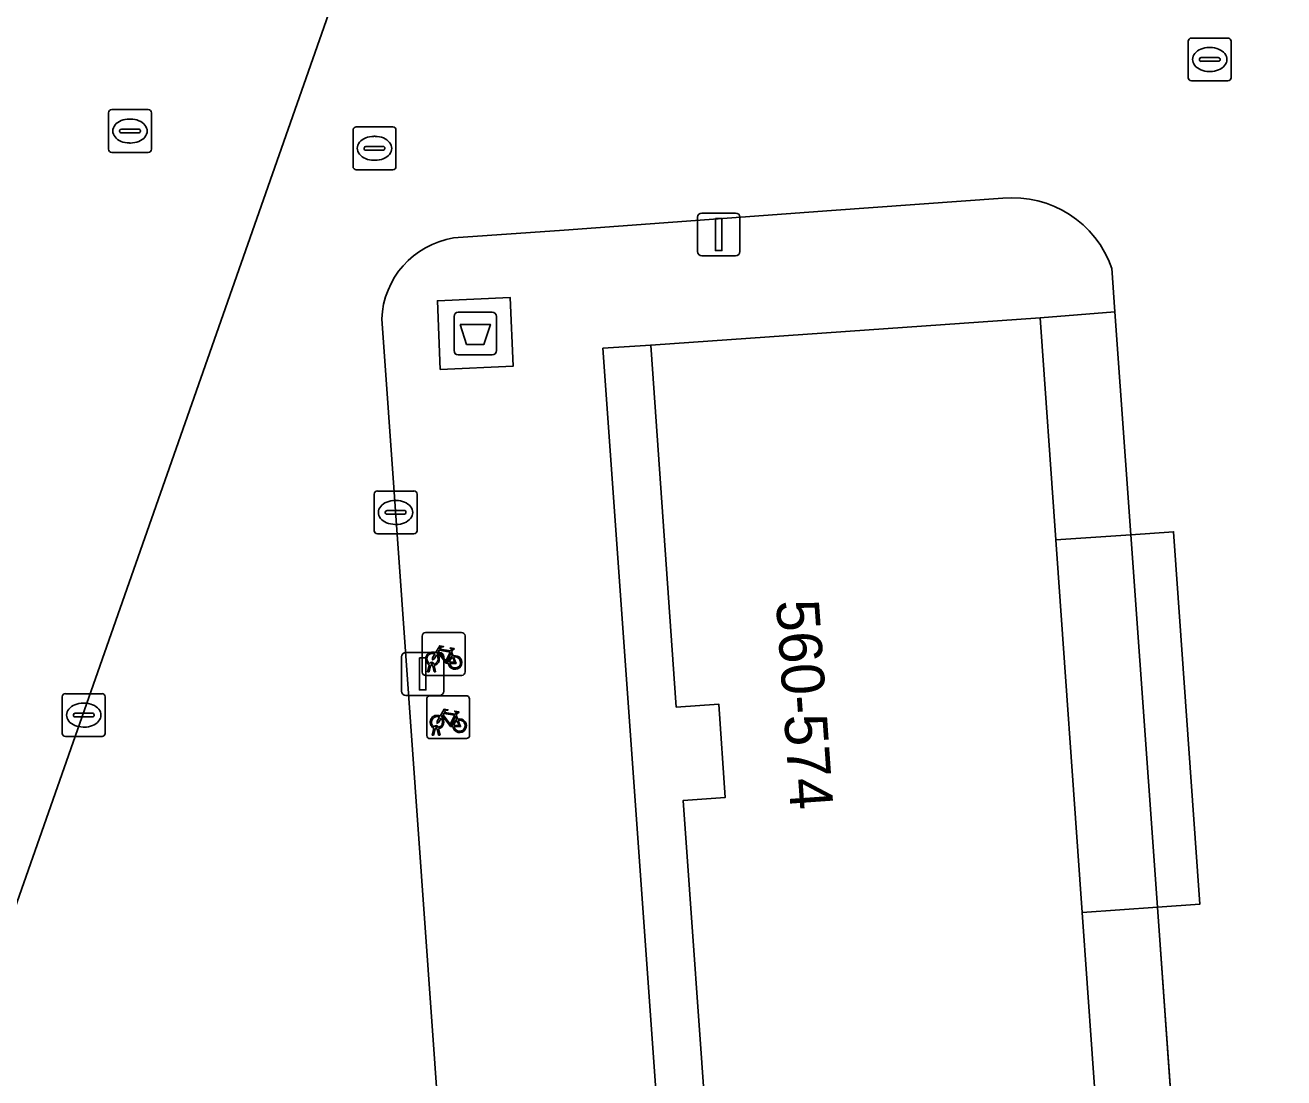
# Model space of a CAD drawing. Extents: x 161248 to 161848, y 384871 to 385383.
# Drawn here: x 161748.82 to 161778.18, y 385173.89 to 385198.45 of the extents above; entities that cross this region are included whole.
import ezdxf

# ---------------------------------------------------------------- set-up
doc = ezdxf.new("R2010")
doc.units = 0
for name, color, linetype in [('IMGEO_Afval_apart_plaats', 7, 'Continuous'), ('IMGEO_Fietsenrek', 7, 'Continuous'), ('IMGEO_Kolk', 7, 'Continuous'), ('IMGEO_Lichtmast', 7, 'Continuous'), ('IMGEO_Pand', 7, 'Continuous'), ('IMGEO_Pand_nummerreeks', 7, 'Continuous'), ('IMGEO_Pand_overbouw', 7, 'Continuous'), ('IMGEO_Rijbaan_lokaal_open', 7, 'Continuous'), ('IMGEO_Rioolput', 7, 'Continuous'), ('IMGEO_Voetpad_gesloten', 7, 'Continuous'), ('IMGEO_Voetpad_open', 7, 'Continuous')]:
    doc.layers.add(name, color=color, linetype=linetype)

msp = doc.modelspace()

# ---------------------------------------------------------------- linework, layer by layer
at = {"layer": 'IMGEO_Afval_apart_plaats'}
for p, q in [((161758.924, 385191.757), (161759.714, 385191.757)), ((161759.714, 385191.757), (161758.924, 385191.757)), ((161758.824, 385190.857), (161758.824, 385191.657)), ((161758.824, 385191.657), (161758.824, 385190.857)), ((161759.814, 385191.657), (161759.814, 385190.857)), ((161759.814, 385190.857), (161759.814, 385191.657)), ((161759.714, 385190.757), (161758.924, 385190.757)), ((161758.924, 385190.757), (161759.714, 385190.757))]:
    msp.add_line(p, q, dxfattribs=at)
msp.add_lwpolyline([(161758.967, 385191.471), (161759.671, 385191.471), (161759.522, 385191.001), (161759.116, 385191.001), (161758.967, 385191.471)], dxfattribs=at)
for centre, start, end in [((161758.924, 385191.657), 90, 180), ((161758.924, 385191.657), 90, 180), ((161759.714, 385191.657), 0, 90), ((161759.714, 385191.657), 360, 90), ((161758.924, 385190.857), 180, 270), ((161758.924, 385190.857), 180, 270), ((161759.714, 385190.857), 270, 0), ((161759.714, 385190.857), 270, 0)]:
    msp.add_arc(centre, 0.1, start, end, dxfattribs=at)
at = {"layer": 'IMGEO_Fietsenrek'}
for p, q in [((161758.081, 385183.355), (161758.081, 385184.196)), ((161758.081, 385184.196), (161758.081, 385183.355)), ((161758.156, 385184.28), (161758.997, 385184.28)), ((161758.997, 385184.28), (161758.156, 385184.28)), ((161759.081, 385184.205), (161759.081, 385183.364)), ((161759.081, 385183.364), (161759.081, 385184.205)), ((161758.768, 385183.829), (161758.804, 385183.734)), ((161758.208, 385183.364), (161758.247, 385183.524)), ((161758.277, 385183.512), (161758.242, 385183.364)), ((161758.319, 385183.536), (161758.318, 385183.54)), ((161758.36, 385183.364), (161758.326, 385183.506)), ((161758.35, 385183.547), (161758.351, 385183.54)), ((161758.358, 385183.51), (161758.393, 385183.364)), ((161759.006, 385183.28), (161758.165, 385183.28)), ((161758.165, 385183.28), (161759.006, 385183.28)), ((161758.242, 385183.364), (161758.208, 385183.364)), ((161758.393, 385183.364), (161758.36, 385183.364)), ((161758.186, 385181.879), (161758.186, 385182.72)), ((161758.186, 385182.72), (161758.186, 385181.879)), ((161758.261, 385182.804), (161759.102, 385182.804)), ((161759.102, 385182.804), (161758.261, 385182.804)), ((161759.186, 385182.729), (161759.186, 385181.888)), ((161759.186, 385181.888), (161759.186, 385182.729)), ((161758.873, 385182.353), (161758.909, 385182.258)), ((161758.313, 385181.888), (161758.352, 385182.048)), ((161758.382, 385182.036), (161758.347, 385181.888)), ((161758.424, 385182.06), (161758.423, 385182.064)), ((161758.465, 385181.888), (161758.431, 385182.03)), ((161758.455, 385182.071), (161758.456, 385182.064)), ((161758.463, 385182.034), (161758.498, 385181.888)), ((161759.111, 385181.804), (161758.27, 385181.804)), ((161758.27, 385181.804), (161759.111, 385181.804)), ((161758.347, 385181.888), (161758.313, 385181.888)), ((161758.498, 385181.888), (161758.465, 385181.888))]:
    msp.add_line(p, q, dxfattribs=at)
for points in [[(161758.415, 385183.754), (161758.363, 385183.664), (161758.323, 385183.639), (161758.324, 385183.686), (161758.379, 385183.78)], [(161758.394, 385183.806), (161758.489, 385183.97), (161758.575, 385183.956), (161758.577, 385183.947), (161758.521, 385183.936), (161758.494, 385183.891), (161758.75, 385183.85)], [(161758.69, 385183.562), (161758.64, 385183.562), (161758.449, 385183.813), (161758.43, 385183.781)], [(161758.737, 385183.825), (161758.48, 385183.866), (161758.463, 385183.837), (161758.63, 385183.617), (161758.737, 385183.825)], [(161758.785, 385183.727), (161758.755, 385183.804), (161758.646, 385183.586), (161758.689, 385183.586)], [(161758.75, 385183.85), (161758.775, 385183.899), (161758.769, 385183.903), (161758.746, 385183.907), (161758.734, 385183.914), (161758.733, 385183.917), (161758.735, 385183.922), (161758.83, 385183.907), (161758.832, 385183.897), (161758.822, 385183.884), (161758.81, 385183.878), (161758.796, 385183.884), (161758.768, 385183.829)], [(161758.719, 385183.586), (161758.839, 385183.585), (161758.795, 385183.699)], [(161758.815, 385183.706), (161758.87, 385183.561), (161758.72, 385183.561)], [(161758.52, 385182.278), (161758.468, 385182.188), (161758.428, 385182.163), (161758.429, 385182.21), (161758.484, 385182.304)], [(161758.499, 385182.33), (161758.594, 385182.494), (161758.68, 385182.48), (161758.682, 385182.471), (161758.626, 385182.46), (161758.599, 385182.415), (161758.855, 385182.374)], [(161758.795, 385182.086), (161758.745, 385182.086), (161758.554, 385182.337), (161758.535, 385182.305)], [(161758.842, 385182.349), (161758.585, 385182.39), (161758.568, 385182.361), (161758.735, 385182.141), (161758.842, 385182.349)], [(161758.89, 385182.251), (161758.86, 385182.328), (161758.751, 385182.11), (161758.794, 385182.11)], [(161758.855, 385182.374), (161758.88, 385182.423), (161758.874, 385182.427), (161758.851, 385182.431), (161758.839, 385182.438), (161758.838, 385182.441), (161758.84, 385182.446), (161758.935, 385182.431), (161758.937, 385182.421), (161758.927, 385182.408), (161758.915, 385182.402), (161758.901, 385182.408), (161758.873, 385182.353)], [(161758.824, 385182.11), (161758.944, 385182.109), (161758.9, 385182.223)], [(161758.92, 385182.23), (161758.975, 385182.085), (161758.825, 385182.085)]]:
    msp.add_lwpolyline(points, dxfattribs=at)
for centre, radius, start, end in [((161758.159, 385184.202), 0.0779, 92.4484, 184.2845), ((161758.159, 385184.202), 0.0779, 92.4484, 184.2845), ((161759.003, 385184.202), 0.0779, 2.4484, 94.2845), ((161759.003, 385184.202), 0.0779, 2.4484, 94.2845), ((161758.321, 385183.665), 0.159, 62.6766, 242.1369), ((161758.321, 385183.665), 0.129, 63.3192, 238.903), ((161758.321, 385183.665), 0.129, 283.6043, 43.4302), ((161758.321, 385183.665), 0.159, 283.5766, 46.6042), ((161758.848, 385183.581), 0.159, 187.0065, 105.7708), ((161758.301, 385183.536), 0.0499, 12.8025, 158.6934), ((161758.321, 385183.665), 0.159, 253.9967, 271.7867), ((161758.301, 385183.536), 0.0174, 12.8025, 163.4502), ((161758.321, 385183.665), 0.129, 253.415, 269.0204), ((161758.848, 385183.581), 0.159, 113.3408, 178.3217), ((161758.848, 385183.581), 0.129, 113.923, 177.9556), ((161758.848, 385183.581), 0.129, 188.6715, 104.5883), ((161758.159, 385183.358), 0.0779, 182.4484, 274.2845), ((161758.159, 385183.358), 0.0779, 182.4484, 274.2845), ((161759.003, 385183.358), 0.0779, 272.4484, 4.2845), ((161759.003, 385183.358), 0.0779, 272.4484, 4.2845), ((161758.264, 385182.726), 0.0779, 92.4484, 184.2845), ((161758.264, 385182.726), 0.0779, 92.4484, 184.2845), ((161759.108, 385182.726), 0.0779, 2.4484, 94.2845), ((161759.108, 385182.726), 0.0779, 2.4484, 94.2845), ((161758.426, 385182.189), 0.159, 62.6766, 242.1369), ((161758.426, 385182.189), 0.129, 63.3192, 238.903), ((161758.426, 385182.189), 0.129, 283.6043, 43.4302), ((161758.426, 385182.189), 0.159, 283.5766, 46.6042), ((161758.406, 385182.06), 0.0499, 12.8025, 158.6934), ((161758.426, 385182.189), 0.159, 253.9967, 271.7867), ((161758.406, 385182.06), 0.0174, 12.8025, 163.4502), ((161758.426, 385182.189), 0.129, 253.415, 269.0204), ((161758.953, 385182.105), 0.159, 113.3408, 178.3217), ((161758.953, 385182.105), 0.159, 187.0065, 105.7708), ((161758.953, 385182.105), 0.129, 113.923, 177.9556), ((161758.953, 385182.105), 0.129, 188.6715, 104.5883), ((161758.264, 385181.882), 0.0779, 182.4484, 274.2845), ((161758.264, 385181.882), 0.0779, 182.4484, 274.2845), ((161759.108, 385181.882), 0.0779, 272.4484, 4.2845), ((161759.108, 385181.882), 0.0779, 272.4484, 4.2845)]:
    msp.add_arc(centre, radius, start, end, dxfattribs=at)
at = {"layer": 'IMGEO_Kolk'}
for p, q in [((161757.035, 385187.582), (161757.887, 385187.582)), ((161756.96, 385186.656), (161756.96, 385187.508)), ((161757.448, 385187.362), (161757.473, 385187.362)), ((161757.961, 385187.508), (161757.961, 385186.656)), ((161757.219, 385187.076), (161757.219, 385187.088)), ((161757.657, 385187.039), (161757.259, 385187.039)), ((161757.262, 385187.125), (161757.66, 385187.125)), ((161757.703, 385187.088), (161757.703, 385187.076)), ((161757.471, 385186.802), (161757.446, 385186.802)), ((161757.887, 385186.582), (161757.035, 385186.582)), ((161749.686, 385181.927), (161749.686, 385182.779)), ((161749.761, 385182.853), (161750.613, 385182.853)), ((161750.174, 385182.633), (161750.199, 385182.633)), ((161750.687, 385182.779), (161750.687, 385181.927)), ((161749.945, 385182.347), (161749.945, 385182.359)), ((161750.383, 385182.31), (161749.985, 385182.31)), ((161749.988, 385182.396), (161750.386, 385182.396)), ((161750.429, 385182.359), (161750.429, 385182.347)), ((161750.197, 385182.073), (161750.172, 385182.073)), ((161750.613, 385181.853), (161749.761, 385181.853))]:
    msp.add_line(p, q, dxfattribs=at)
for points in [[(161757.035, 385187.582), (161757.887, 385187.582)], [(161756.96, 385186.656), (161756.96, 385187.508)], [(161757.961, 385187.508), (161757.961, 385186.656)], [(161757.887, 385186.582), (161757.035, 385186.582)], [(161749.686, 385181.927), (161749.686, 385182.779)], [(161749.761, 385182.853), (161750.613, 385182.853)], [(161750.687, 385182.779), (161750.687, 385181.927)], [(161750.613, 385181.853), (161749.761, 385181.853)]]:
    msp.add_lwpolyline(points, dxfattribs=at)
for centre, radius, start, end in [((161757.037, 385187.506), 0.0765, 91.552, 178.448), ((161757.037, 385187.506), 0.0765, 91.552, 178.448), ((161757.885, 385187.506), 0.0765, 1.552, 88.448), ((161757.885, 385187.506), 0.0765, 1.552, 88.448), ((161757.259, 385187.085), 0.0403, 85.8775, 175.7526), ((161757.256, 385187.075), 0.0366, 178.938, 274.7102), ((161757.66, 385187.082), 0.043, 264.8664, 352.4533), ((161757.664, 385187.087), 0.0386, 1.7309, 96.639), ((161757.037, 385186.658), 0.0765, 181.552, 268.448), ((161757.037, 385186.658), 0.0765, 181.552, 268.448), ((161757.885, 385186.658), 0.0765, 271.552, 358.448), ((161757.885, 385186.658), 0.0765, 271.552, 358.448), ((161749.763, 385182.777), 0.0765, 91.552, 178.448), ((161749.763, 385182.777), 0.0765, 91.552, 178.448), ((161750.611, 385182.777), 0.0765, 1.552, 88.448), ((161750.611, 385182.777), 0.0765, 1.552, 88.448), ((161749.985, 385182.356), 0.0403, 85.8775, 175.7526), ((161749.982, 385182.346), 0.0366, 178.938, 274.7102), ((161750.386, 385182.353), 0.043, 264.8664, 352.4533), ((161750.39, 385182.358), 0.0386, 1.7309, 96.639), ((161749.763, 385181.929), 0.0765, 181.552, 268.448), ((161749.763, 385181.929), 0.0765, 181.552, 268.448), ((161750.611, 385181.929), 0.0765, 271.552, 358.448), ((161750.611, 385181.929), 0.0765, 271.552, 358.448)]:
    msp.add_arc(centre, radius, start, end, dxfattribs=at)
for centre, major_axis, ratio, start_param, end_param in [((161757.447, 385187.082), (-0.387, 0.002), 0.722429, 4.712389, 7.853982), ((161757.472, 385187.082), (-0.39, 0.002), 0.717154, 1.570796, 4.712389), ((161750.173, 385182.353), (-0.387, 0.002), 0.722429, 4.712389, 7.853982), ((161750.198, 385182.353), (-0.39, 0.002), 0.717154, 1.570796, 4.712389)]:
    msp.add_ellipse(centre, major_axis=major_axis, ratio=ratio, start_param=start_param, end_param=end_param, dxfattribs=at)
at = {"layer": 'IMGEO_Lichtmast'}
for p, q in [((161764.602, 385194.069), (161765.392, 385194.069)), ((161765.392, 385194.069), (161764.602, 385194.069)), ((161764.502, 385193.169), (161764.502, 385193.969)), ((161764.502, 385193.969), (161764.502, 385193.169)), ((161765.492, 385193.969), (161765.492, 385193.169)), ((161765.492, 385193.169), (161765.492, 385193.969)), ((161765.392, 385193.069), (161764.602, 385193.069)), ((161764.602, 385193.069), (161765.392, 385193.069)), ((161757.697, 385183.814), (161758.487, 385183.814)), ((161758.487, 385183.814), (161757.697, 385183.814)), ((161757.597, 385182.914), (161757.597, 385183.714)), ((161757.597, 385183.714), (161757.597, 385182.914)), ((161758.587, 385183.714), (161758.587, 385182.914)), ((161758.587, 385182.914), (161758.587, 385183.714)), ((161758.487, 385182.814), (161757.697, 385182.814)), ((161757.697, 385182.814), (161758.487, 385182.814))]:
    msp.add_line(p, q, dxfattribs=at)
for points in [[(161764.922, 385193.944), (161765.072, 385193.944), (161765.072, 385193.194), (161764.922, 385193.194), (161764.922, 385193.944)], [(161758.017, 385183.689), (161758.167, 385183.689), (161758.167, 385182.939), (161758.017, 385182.939), (161758.017, 385183.689)]]:
    msp.add_lwpolyline(points, dxfattribs=at)
for centre, start, end in [((161764.602, 385193.969), 90, 180), ((161764.602, 385193.969), 90, 180), ((161765.392, 385193.969), 0, 90), ((161765.392, 385193.969), 360, 90), ((161764.602, 385193.169), 180, 270), ((161764.602, 385193.169), 180, 270), ((161765.392, 385193.169), 270, 0), ((161765.392, 385193.169), 270, 0), ((161757.697, 385183.714), 90, 180), ((161757.697, 385183.714), 90, 180), ((161758.487, 385183.714), 0, 90), ((161758.487, 385183.714), 360, 90), ((161757.697, 385182.914), 180, 270), ((161757.697, 385182.914), 180, 270), ((161758.487, 385182.914), 270, 0), ((161758.487, 385182.914), 270, 0)]:
    msp.add_arc(centre, 0.1, start, end, dxfattribs=at)
at = {"layer": 'IMGEO_Pand'}
msp.add_lwpolyline([(161772.863, 385186.439), (161772.498, 385191.626), (161763.412, 385190.986), (161764.007, 385182.541), (161764.997, 385182.611), (161765.15, 385180.433), (161764.17, 385180.364), (161764.748, 385172.162), (161773.824, 385172.802), (161773.475, 385177.751)], close=True, dxfattribs=at)
at = {"layer": 'IMGEO_Pand_overbouw'}
for points in [[(161774.609, 385186.562), (161774.237, 385191.764), (161772.498, 385191.626), (161772.863, 385186.439), (161773.475, 385177.751), (161773.824, 385172.802), (161775.583, 385172.925), (161775.229, 385177.875)], [(161764.997, 385182.611), (161764.007, 385182.541), (161763.412, 385190.986), (161762.298, 385190.913), (161763.638, 385172.084), (161764.748, 385172.162), (161764.17, 385180.364), (161765.15, 385180.433)]]:
    msp.add_lwpolyline(points, close=True, dxfattribs=at)
at = {"layer": 'IMGEO_Rijbaan_lokaal_open'}
for points in [[(161730.177, 385124.632), (161736.996, 385144.544), (161740.956, 385156.108), (161742.83, 385161.454), (161757.564, 385203.488), (161757.857, 385204.325), (161760.395, 385211.566), (161765.249, 385225.382), (161768.452, 385234.5), (161773.897, 385250), (161777.978, 385261.406), (161780.943, 385269.693), (161785.276, 385281.802), (161785.52, 385282.473), (161785.703, 385283.163), (161785.823, 385283.866), (161785.88, 385284.578), (161785.874, 385285.292), (161785.803, 385286.002), (161785.673, 385286.689), (161785.312, 385289.733), (161785.296, 385289.929), (161784.343, 385297.154)], [(161757.857, 385204.325), (161757.564, 385203.488), (161742.83, 385161.454), (161759.202, 385162.654), (161758.842, 385167.667), (161757.138, 385191.597)], [(161758.811, 385193.486), (161761.389, 385193.667), (161763.401, 385193.815), (161767.63, 385194.127), (161771.625, 385194.413)], [(161774.165, 385192.778), (161774.237, 385191.764), (161774.609, 385186.562), (161775.608, 385186.633), (161776.22, 385177.945), (161775.229, 385177.875), (161775.933, 385168.029), (161776.914, 385168.098), (161777.526, 385159.401), (161776.554, 385159.332), (161777.256, 385149.507), (161778.218, 385149.575), (161778.83, 385140.897), (161777.876, 385140.83), (161778.263, 385135.406), (161778.562, 385131.184), (161779.901, 385131.276)]]:
    msp.add_lwpolyline(points, dxfattribs=at)
msp.add_lwpolyline([(161775.229, 385177.875), (161776.22, 385177.945), (161775.608, 385186.633), (161774.609, 385186.562)], close=True, dxfattribs=at)
for centre, radius, start, end in [((161771.859, 385191.986), 2.438, 18.9534, 95.5078), ((161759.133, 385191.515), 1.997, 99.2802, 177.6601)]:
    msp.add_arc(centre, radius, start, end, dxfattribs=at)
at = {"layer": 'IMGEO_Rioolput'}
for p, q in [((161776.024, 385198.151), (161776.876, 385198.151)), ((161775.949, 385197.225), (161775.949, 385198.077)), ((161776.437, 385197.931), (161776.462, 385197.931)), ((161776.95, 385198.077), (161776.95, 385197.225)), ((161776.208, 385197.645), (161776.208, 385197.657)), ((161776.646, 385197.608), (161776.248, 385197.608)), ((161776.251, 385197.694), (161776.649, 385197.694)), ((161776.692, 385197.657), (161776.692, 385197.645)), ((161776.46, 385197.371), (161776.435, 385197.371)), ((161776.876, 385197.151), (161776.024, 385197.151)), ((161750.765, 385195.556), (161750.765, 385196.408)), ((161750.84, 385196.482), (161751.692, 385196.482)), ((161751.766, 385196.408), (161751.766, 385195.556)), ((161751.253, 385196.262), (161751.278, 385196.262)), ((161756.543, 385196.078), (161757.395, 385196.078)), ((161751.024, 385195.976), (161751.024, 385195.988)), ((161751.462, 385195.939), (161751.064, 385195.939)), ((161751.067, 385196.025), (161751.465, 385196.025)), ((161751.508, 385195.988), (161751.508, 385195.976)), ((161756.468, 385195.152), (161756.468, 385196.004)), ((161756.956, 385195.858), (161756.981, 385195.858)), ((161757.469, 385196.004), (161757.469, 385195.152)), ((161751.276, 385195.702), (161751.251, 385195.702)), ((161756.727, 385195.572), (161756.727, 385195.584)), ((161757.165, 385195.535), (161756.767, 385195.535)), ((161756.77, 385195.621), (161757.168, 385195.621)), ((161757.211, 385195.584), (161757.211, 385195.572)), ((161751.692, 385195.482), (161750.84, 385195.482)), ((161756.979, 385195.298), (161756.954, 385195.298)), ((161757.395, 385195.078), (161756.543, 385195.078))]:
    msp.add_line(p, q, dxfattribs=at)
for points in [[(161776.024, 385198.151), (161776.876, 385198.151)], [(161775.949, 385197.225), (161775.949, 385198.077)], [(161776.95, 385198.077), (161776.95, 385197.225)], [(161776.876, 385197.151), (161776.024, 385197.151)], [(161750.765, 385195.556), (161750.765, 385196.408)], [(161750.84, 385196.482), (161751.692, 385196.482)], [(161751.766, 385196.408), (161751.766, 385195.556)], [(161756.543, 385196.078), (161757.395, 385196.078)], [(161756.468, 385195.152), (161756.468, 385196.004)], [(161757.469, 385196.004), (161757.469, 385195.152)], [(161751.692, 385195.482), (161750.84, 385195.482)], [(161757.395, 385195.078), (161756.543, 385195.078)]]:
    msp.add_lwpolyline(points, dxfattribs=at)
for centre, radius, start, end in [((161776.026, 385198.075), 0.0765, 91.552, 178.448), ((161776.026, 385198.075), 0.0765, 91.552, 178.448), ((161776.874, 385198.075), 0.0765, 1.552, 88.448), ((161776.874, 385198.075), 0.0765, 1.552, 88.448), ((161776.248, 385197.654), 0.0403, 85.8775, 175.7526), ((161776.245, 385197.644), 0.0366, 178.938, 274.7102), ((161776.649, 385197.651), 0.043, 264.8664, 352.4533), ((161776.653, 385197.656), 0.0386, 1.7309, 96.639), ((161776.026, 385197.227), 0.0765, 181.552, 268.448), ((161776.026, 385197.227), 0.0765, 181.552, 268.448), ((161776.874, 385197.227), 0.0765, 271.552, 358.448), ((161776.874, 385197.227), 0.0765, 271.552, 358.448), ((161750.842, 385196.406), 0.0765, 91.552, 178.448), ((161750.842, 385196.406), 0.0765, 91.552, 178.448), ((161751.69, 385196.406), 0.0765, 1.552, 88.448), ((161751.69, 385196.406), 0.0765, 1.552, 88.448), ((161756.545, 385196.002), 0.0765, 91.552, 178.448), ((161756.545, 385196.002), 0.0765, 91.552, 178.448), ((161757.393, 385196.002), 0.0765, 1.552, 88.448), ((161757.393, 385196.002), 0.0765, 1.552, 88.448), ((161751.064, 385195.985), 0.0403, 85.8775, 175.7526), ((161751.061, 385195.975), 0.0366, 178.938, 274.7102), ((161751.465, 385195.982), 0.043, 264.8664, 352.4533), ((161751.469, 385195.987), 0.0386, 1.7309, 96.639), ((161750.842, 385195.558), 0.0765, 181.552, 268.448), ((161750.842, 385195.558), 0.0765, 181.552, 268.448), ((161751.69, 385195.558), 0.0765, 271.552, 358.448), ((161751.69, 385195.558), 0.0765, 271.552, 358.448), ((161756.767, 385195.581), 0.0403, 85.8775, 175.7526), ((161756.764, 385195.571), 0.0366, 178.938, 274.7102), ((161757.168, 385195.578), 0.043, 264.8664, 352.4533), ((161757.172, 385195.583), 0.0386, 1.7309, 96.639), ((161756.545, 385195.154), 0.0765, 181.552, 268.448), ((161756.545, 385195.154), 0.0765, 181.552, 268.448), ((161757.393, 385195.154), 0.0765, 271.552, 358.448), ((161757.393, 385195.154), 0.0765, 271.552, 358.448)]:
    msp.add_arc(centre, radius, start, end, dxfattribs=at)
for centre, major_axis, ratio, start_param, end_param in [((161776.436, 385197.651), (-0.387, 0.002), 0.722429, 4.712389, 7.853982), ((161776.461, 385197.651), (-0.39, 0.002), 0.717154, 1.570796, 4.712389), ((161751.252, 385195.982), (-0.387, 0.002), 0.722429, 4.712389, 7.853982), ((161751.277, 385195.982), (-0.39, 0.002), 0.717154, 1.570796, 4.712389), ((161756.955, 385195.578), (-0.387, 0.002), 0.722429, 4.712389, 7.853982), ((161756.98, 385195.578), (-0.39, 0.002), 0.717154, 1.570796, 4.712389)]:
    msp.add_ellipse(centre, major_axis=major_axis, ratio=ratio, start_param=start_param, end_param=end_param, dxfattribs=at)
at = {"layer": 'IMGEO_Voetpad_gesloten'}
msp.add_lwpolyline([(161760.134, 385192.094), (161758.436, 385192.022), (161758.504, 385190.42), (161760.202, 385190.492)], close=True, dxfattribs=at)
at = {"layer": 'IMGEO_Voetpad_open'}
for points in [[(161771.625, 385194.413), (161767.63, 385194.127), (161763.401, 385193.815), (161761.389, 385193.667), (161758.811, 385193.486)], [(161764.958, 385153.524), (161763.638, 385172.084), (161762.298, 385190.913), (161763.412, 385190.986), (161772.498, 385191.626), (161774.237, 385191.764), (161774.165, 385192.778)], [(161757.138, 385191.597), (161758.842, 385167.667), (161759.202, 385162.654), (161759.984, 385151.748), (161760.378, 385146.252), (161761.09, 385136.334), (161761.126, 385135.828)]]:
    msp.add_lwpolyline(points, dxfattribs=at)
for points in [[(161758.504, 385190.42), (161758.436, 385192.022), (161760.134, 385192.094), (161760.202, 385190.492)], [(161774.237, 385191.764), (161772.498, 385191.626), (161772.863, 385186.439), (161774.609, 385186.562)], [(161763.638, 385172.084), (161764.748, 385172.162), (161764.17, 385180.364), (161765.15, 385180.433), (161764.997, 385182.611), (161764.007, 385182.541), (161763.412, 385190.986), (161762.298, 385190.913)], [(161774.609, 385186.562), (161772.863, 385186.439), (161773.475, 385177.751), (161775.229, 385177.875)], [(161775.229, 385177.875), (161773.475, 385177.751), (161773.824, 385172.802), (161774.169, 385167.905), (161775.933, 385168.029)]]:
    msp.add_lwpolyline(points, close=True, dxfattribs=at)
for centre, radius, start, end in [((161771.859, 385191.986), 2.438, 18.9534, 95.5078), ((161759.133, 385191.515), 1.997, 99.2802, 177.6601)]:
    msp.add_arc(centre, radius, start, end, dxfattribs=at)

# ---------------------------------------------------------------- texts
at = {"layer": 'IMGEO_Pand_nummerreeks'}
msp.add_text('560-574', height=1, rotation=274.0183, dxfattribs=at).set_placement((161766.332, 385185.015))

doc.saveas('drawing.dxf')
